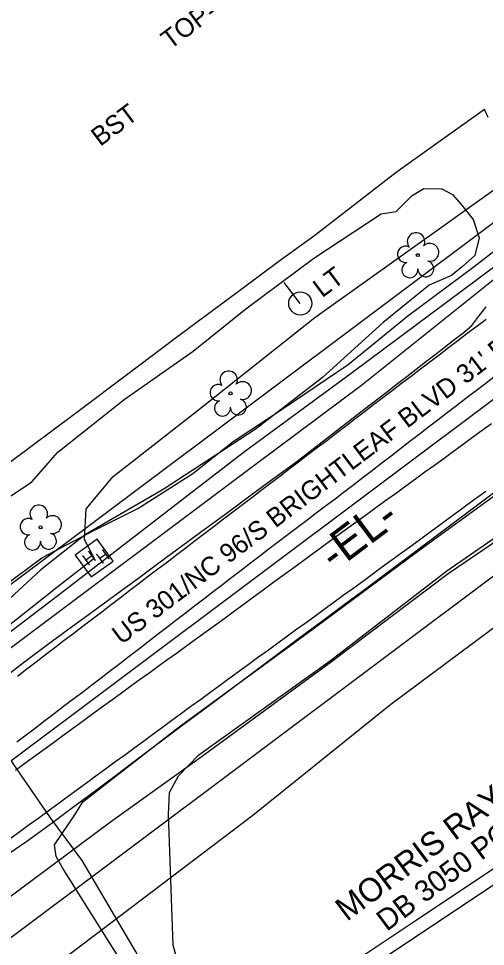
# Model space of a CAD drawing. Extents: x 2186615 to 2188822, y 629899 to 631820.
# Drawn here: x 2188055 to 2188154.1, y 631026.2 to 631223.1 of the extents above; entities that cross this region are included whole.
import ezdxf

# ---------------------------------------------------------------- set-up
doc = ezdxf.new("R2010")
doc.units = 0
for name, color, linetype in [('Exist Horizontal Alignment', 7, 'Continuous'), ('Exist Horizontal Alignment Direction Label', 7, 'Continuous'), ('Exist Property Deed Book Text', 7, 'Continuous'), ('Exist Property Owner Text', 7, 'Continuous'), ('Exist Right of Way Line', 7, 'Continuous'), ('Exist Roads EOP', 7, 'Continuous'), ('Exist Roads EOP Other', 7, 'Continuous'), ('Exist Roads EOP Text', 7, 'Continuous'), ('Exist Roads EOT', 7, 'Continuous'), ('Exist Structure Minor Drop Inlet Top Elevation', 7, 'Continuous'), ('Exist Utilities Gas UG Line SUE LOS B', 7, 'Continuous'), ('Exist Utilities Power Pole CELL', 7, 'Continuous'), ('Exist Utilities Power Pole Text', 7, 'Continuous'), ('Exist Utilities Sanitary Sewer Forced Main SUE LOS B', 7, 'Continuous'), ('Exist Utilities Telephone Hand Hole CELL', 7, 'Continuous'), ('Exist Utilities Telephone UG Cable SUE LOS C', 7, 'Continuous'), ('Exist Utilities Telephone UG FO SUE LOS B', 7, 'Continuous'), ('Exist Utilities Water UG Line SUE LOS B', 7, 'Continuous'), ('Exist Vegetation Hedge Row', 7, 'Continuous'), ('Exist Vegetation Tree CELL', 7, 'Continuous'), ('Exist Vegetation Woods Line', 7, 'Continuous')]:
    doc.layers.add(name, color=color, linetype=linetype)

msp = doc.modelspace()

# ---------------------------------------------------------------- linework, layer by layer
at = {"layer": 'Exist Horizontal Alignment'}
msp.add_line((2187136.41, 630378.11), (2188520.86, 631416.04), dxfattribs=at)
at = {"layer": 'Exist Right of Way Line'}
for p, q in [((2187118.41, 630402.11), (2188502.83, 631440.02)), ((2187154.4, 630354.1), (2188538.85, 631392.04)), ((2187850.54, 630836.34), (2188624.63, 631350.85)), ((2187850.54, 630836.34), (2188371.34, 631182.5)), ((2187850.54, 630836.34), (2188371.34, 631182.5))]:
    msp.add_line(p, q, dxfattribs=at)
at = {"layer": 'Exist Roads EOP'}
for points in [[(2188154.64, 631202.06), (2188153.9, 631203.78)], [(2188135.44, 631145.61), (2188137.42, 631147.14), (2188139.4, 631148.67), (2188141.38, 631150.2), (2188143.35, 631151.73), (2188145.33, 631153.26), (2188147.31, 631154.79), (2188149.29, 631156.32), (2188151.18, 631157.95), (2188152.69, 631159.94), (2188154.22, 631161.92)], [(2188051.29, 631082.76), (2188056.06, 631086.41), (2188060.84, 631090.03), (2188065.69, 631093.56), (2188070.55, 631097.09), (2188075.39, 631100.63), (2188080.22, 631104.19), (2188085.05, 631107.75), (2188089.88, 631111.31), (2188094.71, 631114.87), (2188099.54, 631118.42), (2188104.37, 631121.98), (2188109.2, 631125.54), (2188114.03, 631129.11), (2188118.81, 631132.73), (2188123.55, 631136.41), (2188128.3, 631140.08), (2188133.04, 631143.75), (2188135.43, 631145.6)], [(2188157.74, 631123.82), (2188152.94, 631120.21), (2188148.15, 631116.61), (2188143.35, 631113.01), (2188138.55, 631109.41), (2188133.74, 631105.81), (2188128.93, 631102.23), (2188124.11, 631098.65), (2188119.3, 631095.07), (2188114.49, 631091.49), (2188109.68, 631087.9), (2188104.87, 631084.31), (2188100.07, 631080.71), (2188095.27, 631077.12), (2188090.46, 631073.52), (2188085.66, 631069.93), (2188080.85, 631066.34), (2188076.05, 631062.74), (2188071.24, 631059.15), (2188066.44, 631055.55), (2188061.64, 631051.95), (2188056.76, 631048.46), (2188051.85, 631045.02)]]:
    msp.add_lwpolyline(points, dxfattribs=at)
at = {"layer": 'Exist Roads EOP Other'}
msp.add_lwpolyline([(2188153.9, 631203.78), (2188144.55, 631197.15), (2188135.11, 631190.4), (2188127.27, 631184.33), (2188117.85, 631177.03), (2188110.55, 631171.71), (2188101.88, 631165.28), (2188089.35, 631156.04), (2188079.3, 631148.46), (2188066.8, 631139.05), (2188053.17, 631128.89)], dxfattribs=at)
at = {"layer": 'Exist Roads EOT'}
for points in [[(2188054.79, 631083.55), (2188056.77, 631085.07), (2188058.76, 631086.58), (2188060.75, 631088.1), (2188062.73, 631089.62), (2188064.72, 631091.13), (2188066.71, 631092.65), (2188068.69, 631094.17), (2188070.68, 631095.68), (2188072.67, 631097.2), (2188074.66, 631098.71), (2188076.65, 631100.23), (2188078.64, 631101.75), (2188080.62, 631103.26), (2188082.61, 631104.78), (2188084.6, 631106.29), (2188086.59, 631107.81), (2188088.58, 631109.32), (2188090.57, 631110.84), (2188092.56, 631112.35), (2188094.54, 631113.87), (2188096.53, 631115.38), (2188098.52, 631116.9), (2188100.51, 631118.41), (2188102.5, 631119.93), (2188104.49, 631121.44), (2188106.48, 631122.96), (2188108.46, 631124.47), (2188110.45, 631125.99), (2188112.44, 631127.5), (2188114.43, 631129.02), (2188116.42, 631130.53), (2188118.41, 631132.05), (2188120.4, 631133.56), (2188122.38, 631135.08), (2188124.37, 631136.59), (2188126.36, 631138.11), (2188128.35, 631139.62), (2188130.34, 631141.14), (2188132.33, 631142.65), (2188134.32, 631144.17), (2188136.3, 631145.68), (2188138.29, 631147.2), (2188140.28, 631148.71), (2188142.27, 631150.23), (2188144.26, 631151.74), (2188146.25, 631153.25), (2188148.24, 631154.77), (2188150.23, 631156.28), (2188152.23, 631157.78), (2188154.23, 631159.29)], [(2188054.62, 631069.57), (2188056.61, 631071.08), (2188058.6, 631072.59), (2188060.59, 631074.11), (2188062.58, 631075.62), (2188064.57, 631077.13), (2188066.56, 631078.65), (2188068.55, 631080.16), (2188070.54, 631081.67), (2188072.53, 631083.19), (2188074.51, 631084.72), (2188076.49, 631086.24), (2188078.47, 631087.76), (2188080.46, 631089.28), (2188082.44, 631090.81), (2188084.42, 631092.33), (2188086.4, 631093.85), (2188088.39, 631095.38), (2188090.37, 631096.9), (2188092.35, 631098.42), (2188094.34, 631099.94), (2188096.32, 631101.47), (2188098.3, 631102.99), (2188100.28, 631104.51), (2188102.27, 631106.03), (2188104.25, 631107.55), (2188106.23, 631109.08), (2188108.22, 631110.6), (2188110.2, 631112.12), (2188112.19, 631113.63), (2188114.19, 631115.14), (2188116.18, 631116.65), (2188118.17, 631118.16), (2188120.16, 631119.67), (2188122.16, 631121.18), (2188124.15, 631122.69), (2188126.14, 631124.2), (2188128.12, 631125.73), (2188130.1, 631127.25), (2188132.08, 631128.78), (2188134.06, 631130.31), (2188136.04, 631131.83), (2188138.02, 631133.36), (2188140, 631134.88), (2188141.98, 631136.41), (2188143.97, 631137.93), (2188145.95, 631139.45), (2188147.94, 631140.96), (2188149.93, 631142.48), (2188151.92, 631143.99), (2188153.91, 631145.51), (2188155.89, 631147.03)], [(2188054.35, 631063.57), (2188056.37, 631065.04), (2188058.39, 631066.52), (2188060.4, 631067.99), (2188062.42, 631069.47), (2188064.44, 631070.94), (2188066.46, 631072.42), (2188068.48, 631073.89), (2188070.5, 631075.37), (2188072.52, 631076.84), (2188074.54, 631078.32), (2188076.56, 631079.79), (2188078.58, 631081.25), (2188080.61, 631082.71), (2188082.64, 631084.18), (2188084.66, 631085.64), (2188086.69, 631087.11), (2188088.72, 631088.57), (2188090.74, 631090.03), (2188092.77, 631091.5), (2188094.79, 631092.97), (2188096.81, 631094.44), (2188098.83, 631095.92), (2188100.84, 631097.4), (2188102.86, 631098.88), (2188104.88, 631100.35), (2188106.89, 631101.83), (2188108.91, 631103.31), (2188110.93, 631104.79), (2188112.94, 631106.26), (2188114.96, 631107.74), (2188116.98, 631109.22), (2188118.99, 631110.7), (2188121.01, 631112.17), (2188123.04, 631113.64), (2188125.06, 631115.11), (2188127.08, 631116.57), (2188129.11, 631118.04), (2188131.13, 631119.51), (2188133.15, 631120.98), (2188135.18, 631122.44), (2188137.2, 631123.91), (2188139.23, 631125.38), (2188141.25, 631126.85), (2188143.27, 631128.32), (2188145.3, 631129.78), (2188147.32, 631131.26), (2188149.33, 631132.73), (2188151.35, 631134.21), (2188153.37, 631135.69), (2188155.38, 631137.17)], [(2188154.19, 631122.74), (2188152.17, 631121.26), (2188150.16, 631119.79), (2188148.14, 631118.31), (2188146.12, 631116.84), (2188144.1, 631115.36), (2188142.08, 631113.89), (2188140.06, 631112.41), (2188138.05, 631110.93), (2188136.03, 631109.46), (2188134.01, 631107.98), (2188131.99, 631106.51), (2188129.97, 631105.03), (2188127.96, 631103.56), (2188125.94, 631102.08), (2188123.91, 631100.61), (2188121.89, 631099.14), (2188119.87, 631097.67), (2188117.85, 631096.2), (2188115.83, 631094.73), (2188113.81, 631093.26), (2188111.78, 631091.79), (2188109.76, 631090.32), (2188107.74, 631088.85), (2188105.72, 631087.38), (2188103.7, 631085.91), (2188101.68, 631084.43), (2188099.66, 631082.96), (2188097.64, 631081.48), (2188095.62, 631080.01), (2188093.61, 631078.53), (2188091.59, 631077.06), (2188089.57, 631075.58), (2188087.55, 631074.11), (2188085.53, 631072.63), (2188083.51, 631071.16), (2188081.5, 631069.68), (2188079.48, 631068.2), (2188077.46, 631066.72), (2188075.45, 631065.25), (2188073.43, 631063.77), (2188071.41, 631062.29), (2188069.4, 631060.81), (2188067.38, 631059.34), (2188065.36, 631057.86), (2188063.35, 631056.38), (2188061.33, 631054.9), (2188059.31, 631053.42), (2188057.3, 631051.95), (2188055.28, 631050.47), (2188053.26, 631048.99)]]:
    msp.add_lwpolyline(points, dxfattribs=at)
at = {"layer": 'Exist Utilities Gas UG Line SUE LOS B'}
msp.add_lwpolyline([(2188051.96, 631102.7), (2188059.93, 631108.6), (2188070.82, 631114.33), (2188080.3, 631119.13), (2188092.02, 631126.53), (2188100.57, 631133.33), (2188111.14, 631140.34), (2188124.97, 631149.64), (2188137.6, 631159.99), (2188151.69, 631170.44), (2188162.45, 631178.77), (2188174.08, 631187.88), (2188191.92, 631200.6), (2188207.11, 631211.57), (2188219.39, 631219.84), (2188231.62, 631228.2)], dxfattribs=at)
at = {"layer": 'Exist Utilities Power Pole CELL'}
for q in [(2188111.39, 631167.09), (2188114.79, 631162.61)]:
    msp.add_line((2188114.79, 631162.61), q, dxfattribs=at)
msp.add_circle((2188114.79, 631162.61), 2.45, dxfattribs=at)
at = {"layer": 'Exist Utilities Sanitary Sewer Forced Main SUE LOS B'}
msp.add_lwpolyline([(2188052.08, 631035.89), (2188074.5, 631052.61), (2188093.79, 631066.37), (2188121.43, 631086.62), (2188146.17, 631105.29), (2188183, 631130.32), (2188212.25, 631151.9), (2188236.06, 631169.55), (2188274.9, 631197.79), (2188300.59, 631215.98), (2188344.72, 631249.04), (2188387.13, 631281.33), (2188437.44, 631319.58), (2188480.75, 631351.94), (2188530.77, 631388.8), (2188537.37, 631394.07)], dxfattribs=at)
at = {"layer": 'Exist Utilities Telephone Hand Hole CELL'}
for p, q in [((2188071.69, 631112.58), (2188067.06, 631109.2)), ((2188075.06, 631107.95), (2188071.69, 631112.58)), ((2188067.06, 631109.2), (2188070.43, 631104.58)), ((2188071.06, 631108.58), (2188071.06, 631108.58)), ((2188070.43, 631104.58), (2188075.06, 631107.95))]:
    msp.add_line(p, q, dxfattribs=at)
at = {"layer": 'Exist Utilities Telephone UG Cable SUE LOS C'}
for points in [[(2188096.88, 630993.34), (2188080.22, 631017.51), (2188064.37, 631042.87), (2188062.98, 631045.24), (2188062.65, 631047.71), (2188067.09, 631054.3), (2188068.63, 631056.84), (2188089.09, 631072.74), (2188116.44, 631092.81), (2188141.03, 631110.94), (2188178.22, 631138.01), (2188229.96, 631175.9), (2188269.4, 631205.59), (2188294.58, 631224.2), (2188340.11, 631258.2), (2188382.72, 631289.85), (2188432.93, 631327.36), (2188477.32, 631360.56), (2188524.82, 631398.08), (2188530.94, 631402.62)], [(2188094.37, 630991.41), (2188096.88, 630993.34), (2188087.79, 631026.43), (2188086.82, 631054.16), (2188087.06, 631058.84), (2188088.93, 631062.35), (2188093.27, 631066.84), (2188121.22, 631086.85), (2188145.88, 631105.9), (2188182.55, 631131.21), (2188212.13, 631152.41), (2188236.63, 631168.55), (2188279.23, 631192.06), (2188292.43, 631201.57), (2188302.49, 631212.36), (2188347.67, 631244.49), (2188388.98, 631278.39), (2188439.32, 631316.4), (2188482.92, 631349.33), (2188532.32, 631387.1), (2188539.16, 631391.7)], [(2188096.88, 630993.34), (2188079.83, 631025.19), (2188068.51, 631044.39), (2188061.79, 631053.43), (2188045.22, 631077.41), (2188041.6, 631082.29), (2188043.38, 631085.49), (2188063.96, 631101.13), (2188102.69, 631130.96), (2188125.87, 631148.05), (2188163, 631175.72), (2188217.3, 631215.55), (2188224.13, 631221.73), (2188223.64, 631224.04), (2188219.58, 631228.63), (2188214.19, 631233.71)]]:
    msp.add_lwpolyline(points, dxfattribs=at)
at = {"layer": 'Exist Utilities Telephone UG FO SUE LOS B'}
msp.add_lwpolyline([(2187859.07, 630951.55), (2187882.76, 630968.07), (2187903.06, 630983.05), (2187928.09, 631001.38), (2187948.02, 631018.93), (2187983.82, 631042.28), (2188016.23, 631068.08), (2188049.6, 631091.76), (2188063.06, 631102.31), (2188071.06, 631108.58), (2188069.02, 631112.49), (2188069.37, 631119.05), (2188075.07, 631125.87), (2188092.55, 631139.53), (2188117.88, 631159.65), (2188156.33, 631187.11), (2188185.96, 631206.22), (2188210.21, 631221.29), (2188233.48, 631238.15), (2188251.53, 631251.3), (2188274.73, 631269.24), (2188303.07, 631290.83)], dxfattribs=at)
at = {"layer": 'Exist Utilities Water UG Line SUE LOS B'}
msp.add_lwpolyline([(2187858.58, 630939.62), (2187877.52, 630954.54), (2187897.98, 630970.72), (2187926.28, 630993.39), (2187953.07, 631014.11), (2187986.18, 631039.09), (2188018.97, 631064.16), (2188052.07, 631088.62), (2188105.21, 631128.41), (2188127.75, 631145.3), (2188164.18, 631174.44), (2188192.98, 631196.26), (2188209.23, 631208.45), (2188231.7, 631224.75), (2188257.48, 631242.51), (2188270.74, 631252.18), (2188280.66, 631259.06), (2188311.2, 631281.93)], dxfattribs=at)
at = {"layer": 'Exist Vegetation Hedge Row'}
for points in [[(2188103.26, 631161.48), (2188117.68, 631172.24), (2188131.97, 631181.64), (2188135.15, 631182.12), (2188138.54, 631185.51), (2188140.98, 631187.04), (2188144.86, 631186.94), (2188147.08, 631185.74), (2188149, 631183.56), (2188151.5, 631180.45), (2188152.73, 631176.52), (2188151.8, 631172.81), (2188149.22, 631170.44), (2188146.91, 631168.58), (2188142.16, 631166.48), (2188132.35, 631158.57), (2188119.49, 631146.93), (2188105.24, 631135.9), (2188085.68, 631123.12), (2188069.22, 631113.61), (2188059.73, 631106.06), (2188046.44, 631093.82)], [(2188047.53, 631117.93), (2188057.82, 631124.78), (2188063.33, 631131.06), (2188077.44, 631142.23), (2188092.03, 631152.51), (2188103.26, 631161.48)]]:
    msp.add_lwpolyline(points, dxfattribs=at)
at = {"layer": 'Exist Vegetation Tree CELL'}
for p, q in [((2188139.74, 631172.87), (2188139.74, 631172.87)), ((2188099.98, 631143.54), (2188099.98, 631143.54)), ((2188059.68, 631115.09), (2188059.68, 631115.09))]:
    msp.add_line(p, q, dxfattribs=at)
for centre in [(2188139.74, 631172.87), (2188099.98, 631143.54), (2188059.68, 631115.09)]:
    msp.add_circle(centre, 0.326, dxfattribs=at)
for centre, radius, start, end in [((2188139.36, 631175.75), 1.86, 330.1651, 219.7134), ((2188142.29, 631173.46), 1.9, 257.1011, 134.1999), ((2188137.14, 631173.03), 1.73, 62.6636, 279.3457), ((2188138.04, 631169.75), 1.69, 111.5671, 6.231), ((2188141.42, 631169.98), 1.7, 181.2822, 74.56), ((2188099.6, 631146.41), 1.86, 330.1651, 219.7134), ((2188097.38, 631143.69), 1.73, 62.6636, 279.3457), ((2188102.53, 631144.12), 1.9, 257.1011, 134.1999), ((2188098.28, 631140.41), 1.69, 111.5671, 6.231), ((2188101.65, 631140.64), 1.7, 181.2822, 74.56), ((2188059.3, 631117.97), 1.86, 330.1651, 219.7134), ((2188057.08, 631115.25), 1.73, 62.6636, 279.3457), ((2188062.23, 631115.68), 1.9, 257.1011, 134.1999), ((2188057.98, 631111.97), 1.69, 111.5671, 6.231), ((2188061.36, 631112.19), 1.7, 181.2822, 74.56)]:
    msp.add_arc(centre, radius, start, end, dxfattribs=at)
at = {"layer": 'Exist Vegetation Woods Line'}
for points in [[(2187900, 630901.47), (2187930.95, 630926.02), (2187966.57, 630951.75), (2187999.62, 630976.07), (2188035.07, 631001.76), (2188066.4, 631024.95), (2188104.74, 631054.06), (2188133.99, 631077.57), (2188163.27, 631099.35), (2188198, 631125.47), (2188236.07, 631154.15), (2188273.27, 631182), (2188303.14, 631206.11), (2188341.9, 631232.33), (2188374.15, 631253.71), (2188405.25, 631276.99)], [(2188336.81, 631162.74), (2188304.67, 631140.79), (2188253.49, 631107.84), (2188202.91, 631074.1), (2188139.41, 631031.67), (2188093.1, 631000.83), (2188032.1, 630960.3), (2187970.81, 630919.03), (2187899.6, 630870.56), (2187878.91, 630858.57), (2187866.57, 630849.5), (2187856.84, 630841.46), (2187846.68, 630832.19), (2187829.94, 630827.76), (2187807.52, 630819.83), (2187838.54, 630838.9), (2187846.29, 630845.15), (2187849.33, 630854.22), (2187863.66, 630870.01), (2187881.14, 630887.73), (2187900, 630901.47)]]:
    msp.add_lwpolyline(points, dxfattribs=at)

# ---------------------------------------------------------------- texts
at = {"layer": 'Exist Horizontal Alignment Direction Label'}
msp.add_text('-EL-', height=7, rotation=36.9253, dxfattribs=at).set_placement((2188122.06, 631105.66))
at = {"layer": 'Exist Property Deed Book Text'}
msp.add_text('DB 3050 PG 269', height=4.5, rotation=36.8593, dxfattribs=at).set_placement((2188133.13, 631029.24))
at = {"layer": 'Exist Property Owner Text'}
msp.add_text('MORRIS RAY THOMPSON JR, ET AL', height=5, rotation=36.8593, dxfattribs=at).set_placement((2188124.68, 631031.33))
at = {"layer": 'Exist Roads EOP Text'}
for s, rotation, p in [('BST', 36.8593, (2188072.33, 631195.81)), ("US 301/NC 96/S BRIGHTLEAF BLVD 31' BST", 37.1238, (2188076.81, 631090.07))]:
    msp.add_text(s, height=4, rotation=rotation, dxfattribs=at).set_placement(p)
at = {"layer": 'Exist Structure Minor Drop Inlet Top Elevation'}
msp.add_text("TOP=124.78'", height=4, rotation=36.8891, dxfattribs=at).set_placement((2188087.17, 631216.38))
at = {"layer": 'Exist Utilities Power Pole Text'}
msp.add_text('LT', height=4, rotation=36.8593, dxfattribs=at).set_placement((2188119.42, 631163.7))
at = {"layer": 'Exist Utilities Telephone Hand Hole CELL'}
for p in [(2188069.73, 631106.87), (2188072.67, 631107.2)]:
    msp.add_text('H', height=2.5, rotation=36.0796, dxfattribs=at).set_placement(p)

doc.saveas('drawing.dxf')
